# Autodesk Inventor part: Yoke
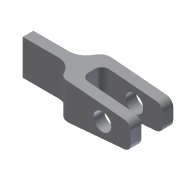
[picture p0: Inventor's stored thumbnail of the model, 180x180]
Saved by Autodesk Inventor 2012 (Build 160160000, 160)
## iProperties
Created: 2012-02
Part Number: Yoke
Material: Default
Document SubType Name: Modeling
Designer: cadcim
Density: 1 g/cm^3
Author: cadcim
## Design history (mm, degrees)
sketch "Sketch1"
  geometry: L1 (-20, 1.5)-(-9.975, 1.5); L2 (-5, 6)-(15, 6); L3 (15, 6)-(15, 3); L4 (15, 3)-(-2, 3); L5 (0, 0)-(-12.291, 0); L6 (-20, -1.5)-(-9.975, -1.5); L7 (-5, -6)-(15, -6); L8 (15, -6)-(15, -3); L9 (15, -3)-(-2, -3); L10 (-20, 1.5)-(-20, -1.5); L11 (-2, 3)-(-2, -3); A1 r 5 centre (-9.975, 6.5) between (-9.975, 1.5) and (-5, 6); A2 r 5 centre (-9.975, -6.5) between (-5, -6) and (-9.975, -1.5)
  constraints: 22 end point, 7 symmetric about line, 4 point on circle, 3 parallel, 2 centre point, 1 horizontal, 1 perpendicular, 1 tangent, 1 other
  dimensions: "d0" = 3 distance of L1.start L6.start; "d1" = 20 distance of L2.start L2.end; "d2" = 6 distance between parallel lines of L9 L4; "d3" = 3 distance of L7.end L8.end; "d4" = 5 radius of A1; "d5" = 35 distance between parallel lines of L10 L8; "d12" = 17 distance of L3.end L4.end
extrude "Extrusion1" new body sketch "Sketch1" stored distance "d8" = 10; taper "d9" = 0 deg
fillet "Fillet1" dims "d10" = 3
fillet "Fillet2" dims "d11" = 2
sketch "Sketch2"
  geometry: L1 (0, 0)-(0, 10) reference; L2 (-17.781, 0)-(0, 0) reference; C1 r 2.5 at (-8, 5); 1 further point
  constraints: 1 centre point
  dimensions: "d13" = 5 diameter of C1; "d16" = 8 distance from line of L1 C1.centre; "d17" = 5 distance from line of C1.centre L2
extrude "Extrusion2" cut sketch "Sketch2" distance "d18" = 20.25; taper "d19" = 0 deg
sketch "Sketch3"
  geometry: L1 (0, 10)-(-17.781, 10) reference; L2 (-17.345, 10)-(0, 8.482); L3 (-17.345, 10)-(0.066, 10); L4 (-17.345, 0)-(0, 1.518); L5 (0, 10)-(0, 8.482); L6 (0, 10)-(-17.345, 10); L7 (0, 0)-(0, 1.518); L8 (0, 0)-(-17.345, 0); 1 further point
  constraints: 14 end point, 1 collinear, 1 equal length, 1 horizontal, 1 perpendicular, 1 point on line
  dimensions: "d20" = 5 deg angle of L2 L3
extrude "Extrusion3" cut sketch "Sketch3" distance "d21" = 49; taper "d22" = 0 deg
fillet "Fillet3" dims "d23" = 2
body "Solid1"
